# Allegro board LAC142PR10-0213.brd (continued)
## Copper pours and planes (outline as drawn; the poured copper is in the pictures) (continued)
LX_VDDP_ALWP on TOP (solid shape): 140.26,149.1 140.26,148.27 140.2,148.21 138.36,148.21 138.23,148.34 137.28,148.34 137.22,148.4 137.22,148.59 137.28,148.65 138.23,148.65 138.3,148.72 139.38,148.72 139.57,148.91 139.57,149.1 139.63,149.16 140.2,149.16
LX_VDDP_ALWP on BOTTOM (solid shape): outline of 157 points within 134.68,129.03 146.87,141.48
LX_VDDP_ALWP on IN2 (solid shape): 139.38,148.59 139.38,147.7 139.06,147.38 138.68,147.38 138.23,147.83 138.23,148.59 138.36,148.72 139.25,148.72
LX_VDDP_ALWP on IN2 (solid shape): 140.26,135.32 140.26,134.75 140.14,134.62 139.12,134.62 138.99,134.75 138.99,135.83 139.19,136.02 139.57,136.02
PHASE_CHG on BOTTOM (solid shape): 135.76,167.32 135.76,162.94 136.45,162.24 137.15,162.24 137.41,161.99 137.41,159.83 137.15,159.58 133.47,159.58 133.15,159.89 133.15,165.42 132.71,165.86 131.57,165.86 131.44,165.99 131.44,167.45 131.63,167.64 135.44,167.64
PHASE_CHG on BOTTOM (solid shape): 119.88,167.08 120.04,167.08 120.12,167.07 120.21,167.08 120.95,167.08 120.95,167.08 121.98,167.08 122,167.06 122,166.19 121.98,166.17 121.31,166.17 120.97,166.5 120.06,166.5 119.6,166.96 118.58,166.96 118.54,167.01 118.54,167.12 118.6,167.18 119.77,167.18
PHASE_CHG on IN2 (solid shape): 133.66,163.58 133.66,162.69 133.53,162.56 132.9,162.56 132.39,163.07 132.39,163.45 132.64,163.7 133.53,163.7
PHASE_CHG on IN2 (solid shape): 121.41,166.94 121.89,166.94 121.96,166.87 121.96,166.26 121.86,166.16 121.51,166.16 121.18,166.5 120.01,166.5 119.88,166.62 119.88,166.88 120.01,167 121.34,167
RING2 on BOTTOM (solid shape): 189.3,21.14 189.3,20.25 189.24,20.19 188.17,20.19 188,20.35 188,21.21 188.11,21.32 189.13,21.32
RING2 on BOTTOM (solid shape): 182.14,18.22 182.14,17.74 183.13,16.75 183.13,15.43 183.08,15.38 182.96,15.38 182.91,15.43 182.91,16.21 182.67,16.45 182.56,16.45 182.21,16.79 181.49,16.79 180.81,17.47 180.81,17.48 180.75,17.54 180.75,18.22 180.86,18.33 182.02,18.33
RING2 on IN2 (solid shape): 182.94,18.92 182.94,18.54 182.56,18.16 182.56,17.53 182.17,17.14 181.79,17.14 181.54,17.4 181.54,18.67 182.17,19.3 182.56,19.3
RING2 on IN2 (solid shape): 188.68,21.21 188.68,20.33 188.55,20.2 187.79,20.2 187.73,20.26 187.67,20.26 187.23,20.7 187.23,21.16 187.38,21.31 188.58,21.31
RING2_R on TOP (solid shape): 192.65,24.78 192.65,23.72 192.35,23.42 190.66,23.42 190.37,23.14 190.37,22.46 190.62,22.21 190.62,21.71 190.58,21.67 190.47,21.51 190.43,21.32 190.43,21.3 190.34,21.21 189.39,21.21 189.2,21.4 189.2,24.62 189.65,25.06 192.37,25.06
RING2_R on BOTTOM (solid shape): 190.47,21.76 190.47,20.59 190.12,20.25 189.5,20.25 189.48,20.27 189.48,21.24 189.3,21.43 189.3,21.68 189.47,21.86 190.37,21.86
SLEEVE on BOTTOM (solid shape): 192.78,14.96 192.78,13.82 192.66,13.7 191.73,13.7 191.62,13.81 191.62,15.03 191.73,15.14 192.6,15.14
SLEEVE on BOTTOM (solid shape): 183.53,20.29 183.53,19.69 183.43,19.58 183.43,17.35 183.56,17.22 183.56,15.47 183.46,15.37 183.38,15.37 183.29,15.46 183.29,16.79 182.4,17.68 182.4,20.13 182.73,20.46 183.37,20.46
SLEEVE on IN1 (solid shape): 184.44,18.37 184.44,17.43 184.31,17.29 183.04,17.29 182.91,17.42 182.91,18.34 183.05,18.48 184.34,18.48
SLEEVE on IN1 (solid shape): 192.82,15.36 192.82,14.59 192.66,14.42 191.7,14.42 191.36,14.76 190.61,14.76 190.46,14.91 190.46,15.75 190.51,15.8 192.39,15.8
SLEEVE_R on TOP (solid shape): 193,13.7 193,13.03 192.74,12.77 190.56,12.77 190.41,12.92 190.41,13.82 190.51,13.93 192.77,13.93
SLEEVE_R on TOP (solid shape): 192.39,27 192.39,26.61 192.33,26.55 192.33,26.12 192.68,25.78 193,25.78 193,25.78 193.61,25.78 193.92,25.47 193.92,25.03 193.81,24.92 192.81,24.92 192.3,25.43 191.23,25.43 190.98,25.67 190.98,26.95 191.12,27.08 192.31,27.08
SLEEVE_R on BOTTOM (solid shape): 192.72,13.54 192.72,13.08 192.64,13 190.68,13 190.48,13.21 190.48,13.44 190.63,13.59 192.67,13.59
SNB_1.35VGPU on BOTTOM (solid shape): 192.47,163.02 192.47,162.13 192.78,161.82 193.81,161.82 193.94,161.7 193.94,160.74 193.87,160.68 191.22,160.68 191.06,160.84 191.06,162.7 191.39,163.03 192.46,163.03
SPK_L+_CONN on TOP (solid shape): 90.13,10.43 90.13,9.24 90.04,9.14 89.44,9.14 88.97,9.61 88.37,9.61 87.68,8.93 86.14,8.93 85.3,9.77 83.97,9.77 83.45,9.25 82.1,9.25 81.87,9.01 81.87,7.35 81.76,7.24 80.72,7.24 80.57,7.4 80.57,9.65 81.63,10.72 89.85,10.72
SPK_L+_CONN on BOTTOM (solid shape): 81.88,7.93 81.88,7.01 81.79,6.92 79.2,6.92 78.89,7.24 77.36,7.24 77.18,7.42 77.18,7.67 77.39,7.87 78.92,7.87 79.01,7.96 81.84,7.96
SPK_L-_CONN on TOP (solid shape): 83.17,8.81 83.17,8.16 83.49,7.85 85.19,7.85 85.95,8.61 87.08,8.61 88.26,7.43 89.06,7.43 89.49,7.86 90.11,7.86 90.14,7.84 90.14,6.85 89.83,6.54 82.41,6.54 82.03,6.93 82.03,8.8 82.17,8.95 83.03,8.95
SPK_L-_CONN on BOTTOM (solid shape): 83.15,9.19 83.15,8.35 83.06,8.27 77.37,8.27 77.17,8.47 77.17,8.71 77.37,8.92 78.56,8.92 79.01,9.37 82.97,9.37
SPK_R+_CONN on TOP (solid shape): 90.14,6.13 90.14,5.21 90.05,5.12 89.45,5.12 89.13,5.44 88.16,5.44 87.51,4.79 85.58,4.79 85.24,5.13 83.59,5.13 82.9,4.44 82.06,4.44 81.94,4.57 81.94,5.99 82.3,6.35 89.92,6.35
SPK_R+_CONN on BOTTOM (solid shape): 79.48,5.01 82.86,5.01 83.02,4.86 83.02,3.92 82.84,3.74 79.06,3.74 77.55,5.25 77.32,5.25 77.17,5.4 77.17,5.72 77.35,5.89 78.59,5.89
SPK_R-_CONN on TOP (solid shape): 81.77,5.79 81.77,5.5 81.77,4.28 82.02,4.03 83.82,4.03 84.05,3.79 84.36,3.71 84.87,3.71 85.18,3.79 85.4,4.03 87.49,4.03 88.11,3.4 88.93,3.4 89.34,3.81 90.09,3.81 90.13,3.77 90.13,2.82 90.04,2.73 84.88,2.73 84.66,2.51 82.96,2.51 82.75,2.73 81.21,2.73 80.32,3.63 80.32,5.81 80.48,5.98 81.58,5.98
SPK_R-_CONN on BOTTOM (solid shape): 79.13,6.69 81.32,6.69 81.56,6.46 81.56,5.5 81.44,5.38 79.57,5.38 78.71,6.24 77.35,6.24 77.18,6.4 77.18,6.73 77.31,6.86 78.96,6.86
T-GND_L on TOP (solid shape): 16.22,172.15 16.22,170.13 16.01,169.93 14.97,169.93 14.86,170.04 14.86,172.04 15.09,172.26 16.11,172.26
T-GND_L on BOTTOM (solid shape): 16.12,172.12 16.12,170.12 15.96,169.95 15.11,169.95 15.04,170.01 15.04,172.14 15.17,172.26 15.98,172.26
T-GND_L on BOTTOM (solid shape): 20.44,164.34 20.44,162.12 20.38,162.05 19.36,162.05 19.23,162.18 19.23,164.4 19.3,164.47 20.31,164.47
T-GND_L on IN1 (solid shape): 16.31,172.32 16.31,170.63 16.11,170.43 15.15,170.43 14.9,170.68 14.9,172.25 15.06,172.41 16.23,172.41
T-GND_L on IN1 (solid shape): 20.58,164.92 20.58,163.96 20.44,163.82 19.37,163.82 19.17,164.02 19.17,164.02 19.04,164.15 19.04,165.39 19.29,165.64 19.87,165.64
UG1_APU on TOP (solid shape): 118.04,142.49 118.04,141.6 117.91,141.48 116.9,141.48 116.64,141.73 116.64,142.62 116.9,142.88 117.66,142.88
UG1_APU on TOP (solid shape): 117.27,152.68 117.27,150.47 117.14,150.33 116.9,150.33 116.81,150.42 116.81,151.27 117.05,151.52 117.05,152.69 117.11,152.75 117.2,152.75
UG1_APU on IN2 (solid shape): 117.28,151.26 117.28,149.61 117.15,149.48 116.64,149.48 116.52,149.61 116.52,150.11 116.77,150.37 116.77,151.26 116.9,151.38 117.15,151.38
UG1_APU on IN2 (solid shape): 118.42,142.88 118.42,142.62 118.04,142.24 116.77,142.24 116.64,142.37 116.64,142.75 116.77,142.88 117.4,142.88 117.79,143.26 118.04,143.26
UG1_GFX on TOP (solid shape): 61.78,47.5 61.78,47.12 61.02,46.35 61.02,45.72 60.89,45.59 60.51,45.59 60.38,45.72 60.38,47.5 60.64,47.75 61.52,47.75
UG1_GFX on TOP (solid shape): 61.4,39.62 61.4,38.73 60.89,38.23 60.89,37.27 60.81,37.2 60.71,37.2 60.64,37.27 60.64,38.42 60.89,38.67 60.89,39.62 61.02,39.75 61.27,39.75
UG1_GFX on IN2 (solid shape): 61.08,46.67 61.08,44.96 61.02,44.89 60.45,44.89 60.32,45.02 60.32,46.61 60.57,46.86 60.89,46.86
UG1_GFX on IN2 (solid shape): 62.03,40.51 62.03,40.07 61.4,39.43 61.4,38.73 61.27,38.61 61.02,38.61 60.89,38.73 60.89,39.69 61.27,40.07 61.27,40.51 61.33,40.58 61.97,40.58
UG1_VGA on BOTTOM (solid shape): 177.22,103 177.22,102.68 176.97,102.43 176.52,102.43 175.89,101.79 175.06,101.79 174.87,101.98 174.87,102.17 175.06,102.36 175.32,102.36 176.14,103.19 177.03,103.19
UG1_VGA on BOTTOM (solid shape): 175,94.07 175,93.8 174.88,93.68 174.02,93.68 173.51,93.17 172.38,93.17 172.3,93.25 172.3,93.33 172.37,93.39 172.99,93.39 172.99,93.39 173.3,93.39 174.09,94.19 174.88,94.19
UG1_VGA on IN2 (solid shape): 176.02,102.11 176.02,101.98 175.06,101.03 174.75,101.03 174.43,101.35 174.43,101.66 175.06,102.3 175.82,102.3
UG1_VGA on IN2 (solid shape): 175,94.55 175,93.85 174.83,93.69 174.02,93.69 173.92,93.79 173.92,94.61 174.17,94.87 174.68,94.87
UG2_VGA on BOTTOM (solid shape): 178.24,89.41 178.24,88.84 178.17,88.77 177.73,88.77 177.54,88.96 176.59,88.96 176.46,89.09 176.46,89.41 176.59,89.53 178.11,89.53
UG2_VGA on BOTTOM (solid shape): 196.02,87.44 196.02,86.99 195.89,86.87 195.51,86.87 194.87,86.23 194.68,86.23 194.37,86.55 194.37,86.99 194.94,87.57 195.89,87.57
UG2_VGA on BOTTOM (solid shape): 174.06,90.25 174.6,90.25 174.81,90.04 174.81,89.79 174.68,89.66 173.82,89.66 173.69,89.79 173.69,90.15 173.47,90.37 172.37,90.37 172.31,90.43 172.31,90.54 172.37,90.59 173.71,90.59
UG2_VGA on IN2 (solid shape): 175.19,89.6 177.48,89.6 177.67,89.41 177.67,88.96 177.54,88.84 174.62,88.84 173.67,89.79 173.67,89.98 173.86,90.17 174.62,90.17
UG_1.35V on TOP (solid shape): 63.94,21.08 63.94,20.83 63.81,20.7 62.92,20.7 62.67,20.95 61.78,20.95 61.72,21.02 61.72,21.15 61.78,21.21 63.81,21.21
UG_1.35V on BOTTOM (solid shape): 71.99,19.81 71.99,18.9 71.87,18.77 71,18.77 70.84,18.94 70.84,19.89 71.03,20.08 71.72,20.08
UG_1.35V on IN2 (solid shape): 64.7,21.27 64.7,20.83 64.57,20.7 62.92,20.7 62.79,20.83 62.79,21.08 63.18,21.46 64.51,21.46
UG_1.35V on IN2 (solid shape): 71.37,19.88 71.37,19.05 71.24,18.92 70.99,18.92 70.86,19.05 70.86,19.24 70.16,19.94 70.16,20.13 70.54,20.51 70.73,20.51
UG_3V on TOP (solid shape): 35.87,42.67 35.87,41.78 35.74,41.66 35.11,41.66 34.85,41.91 34.85,42.67 34.98,42.8 35.74,42.8
UG_3V on TOP (solid shape): 40.95,50.04 40.95,49.91 40.25,49.21 39.3,49.21 39.17,49.34 39.17,49.59 39.36,49.78 39.62,49.78 39.93,50.1 40.89,50.1
UG_3V on IN2 (solid shape): 35.87,43.43 35.87,41.78 35.74,41.66 35.43,41.66 35.3,41.78 35.3,42.67 35.11,42.86 35.11,43.43 35.24,43.56 35.74,43.56
UG_3V on IN2 (solid shape): 40.32,49.66 40.32,49.34 39.74,48.77 39.74,48.58 39.49,48.32 39.3,48.32 39.05,48.58 39.05,49.47 39.3,49.72 40.25,49.72
UG_5V on TOP (solid shape): 45.01,42.67 45.01,41.78 44.89,41.66 44.13,41.66 43.87,41.91 43.87,42.67 44,42.8 44.89,42.8
UG_5V on TOP (solid shape): 44.76,49.59 44.76,49.34 44.63,49.21 43.62,49.21 42.89,49.94 42.89,50.04 42.96,50.1 44.25,50.1
UG_5V on IN2 (solid shape): 45.08,43.4 45.08,41.75 44.95,41.62 44.63,41.62 44.51,41.75 44.51,42.77 44.32,42.96 44.32,43.4 44.38,43.47 45.01,43.47
UG_5V on IN2 (solid shape): 45.71,49.34 45.71,49.02 45.52,48.83 45.08,48.83 44.7,49.21 43.74,49.21 43.62,49.34 43.62,49.59 43.74,49.72 45.33,49.72
UG_NB on TOP (solid shape): 121.9,153.36 122.88,153.36 123.02,153.22 123.02,152.98 122.89,152.85 122.04,152.85 121.68,153.21 120.6,153.21 120.54,153.26 120.54,153.36 120.6,153.42 121.84,153.42
UG_NB on BOTTOM (solid shape): 124.33,141.67 124.33,140.02 124.07,139.76 123.69,139.76 123.5,139.95 123.5,141.6 123.75,141.86 124.14,141.86
UG_NB on IN2 (solid shape): 122.95,153.25 122.95,152.16 122.7,151.9 122.14,151.9 121.9,152.14 121.9,153.22 122.02,153.34 122.87,153.34
UG_NB on IN2 (solid shape): 124.96,141.03 124.96,140.91 124.2,140.14 124.2,139.95 124.07,139.83 123.82,139.83 123.69,139.95 123.69,140.84 124.33,141.48 124.52,141.48
UG_VDDP_ALWP on TOP (solid shape): 139.38,149.22 139.38,148.97 139.25,148.84 137.28,148.84 137.22,148.91 137.22,149.1 137.28,149.16 138.17,149.16 138.36,149.35 139.25,149.35
UG_VDDP_ALWP on TOP (solid shape): 145.41,135.64 145.41,135.38 144.96,134.94 144.96,134.05 144.77,133.86 144.39,133.86 144.27,133.98 144.27,135.64 144.39,135.76 145.28,135.76
UG_VDDP_ALWP on IN2 (solid shape): 145.41,135.95 145.41,135.38 145.22,135.19 144.33,135.19 144.14,135.38 144.14,136.4 144.33,136.59 144.77,136.59
UG_VDDP_ALWP on IN2 (solid shape): 140.2,149.29 140.2,148.97 139.95,148.72 139.63,148.72 139.5,148.84 138.36,148.84 138.23,148.97 138.23,149.22 138.42,149.42 140.07,149.42
UGATE_CHG on BOTTOM (solid shape): 132.58,162.94 132.58,161.86 132.45,161.73 131.57,161.73 131.44,161.86 131.44,162.94 131.57,163.07 132.45,163.07
UGATE_CHG on BOTTOM (solid shape): 119.97,166.37 120.81,166.37 120.95,166.23 120.95,166 120.82,165.88 120.04,165.88 119.44,166.47 119.44,166.47 119.35,166.56 118.59,166.56 118.54,166.61 118.54,166.72 118.58,166.77 119.57,166.77
UGATE_CHG on IN2 (solid shape): 121.53,165.93 121.53,165.61 121.21,165.29 121.02,165.29 120.45,165.86 120.01,165.86 119.88,165.99 119.88,166.24 120.01,166.37 121.09,166.37
UGATE_CHG on IN2 (solid shape): 131.37,162.31 132.45,162.31 132.58,162.18 132.58,161.86 132.45,161.73 130.8,161.73 130.74,161.8 130.74,162.43 130.8,162.5 131.18,162.5
VSUMP_NB on TOP (solid shape): 122.12,157.67 122.12,157.2 122.13,157.19 121.98,157.04 121.75,157.04 121.57,156.86 121.57,156.47 121.49,156.4 120.6,156.4 120.53,156.47 120.53,156.55 120.6,156.62 120.9,156.62 121.6,157.32 121.6,157.65 121.72,157.77 122.01,157.77
N17205206 on BOTTOM (solid shape): 186.37,35.81 186.37,35.12 184.4,33.15 184.27,33.15 184.21,33.21 184.21,34.29 184.37,34.45 184.81,34.45 185.73,35.37 185.73,35.81 185.79,35.88 186.3,35.88
N17382859 on BOTTOM (solid shape): 32.96,51.39 33.41,51.39 33.41,51.88 33.76,51.88 33.76,51.39 34.21,51.39 34.21,51.88 34.66,51.88 34.79,51.75 34.79,50.67 33.71,49.59 33.71,48.32 33.65,48.26 30.66,48.26 30.47,48.45 30.47,50.16 32.19,51.88 32.96,51.88
N17415515 on TOP (solid shape): outline of 103 points within 94.88,157.29 98.84,162.65
N17451409 on TOP (solid shape): 67.93,51.23 68.6,51.23 68.6,50.67 69.14,50.67 69.14,51.22 69.4,51.22 69.4,50.69 69.94,50.69 69.94,51.23 72.57,51.23 72.8,51 72.8,46.35 72.36,45.91 66.22,45.91 65.78,45.47 62.67,45.47 62.54,45.59 62.54,53.21 63.07,53.75 65.41,53.75
N17481633 on BOTTOM (solid shape): 130.36,171.45 130.36,168.15 130.87,167.64 130.87,160.59 130.49,160.21 129.63,160.21 129.63,160.7 128.98,160.7 128.98,160.21 128.43,160.21 128.43,160.7 127.78,160.7 127.78,160.21 127.18,160.21 127.06,160.34 127.06,164.08 127.44,164.47 127.44,171.45 127.5,171.51 130.3,171.51
N19198957 on TOP (solid shape): 19.69,79.68 19.69,79.11 19.51,78.93 17.67,78.93 16.49,80.11 14.75,80.11 14.55,80.31 14.55,81.6 14.65,81.7 17.67,81.7
N20135074 on BOTTOM (solid shape): 177.48,98.36 178.49,98.36 178.56,98.3 178.56,97.73 178.49,97.66 175.44,97.66 175.38,97.73 175.38,98.68 175.44,98.74 177.09,98.74
N20135197 on BOTTOM (solid shape): 189.29,106.36 189.99,105.66 189.99,104.01 188.97,104.01 188.91,104.08 188.91,105.79 188.65,106.04 188.65,106.93 189.29,106.93
N20141406 on TOP (solid shape): 118.47,152.68 118.47,151.63 119.13,150.97 119.13,147.86 119.06,147.79 118.54,147.79 118.46,147.87 118.46,150.06 118.58,150.18 118.58,151.23 118.25,151.55 118.25,152.66 118.33,152.74 118.41,152.74
N20141477 on BOTTOM (solid shape): 133.29,139.63 133.29,137.2 132.94,136.85 131.62,136.85 131.31,137.15 131.31,139.31 131.78,139.78 133.14,139.78
N20141719 on TOP (solid shape): 120.2,144.14 120.2,142.43 120.14,142.37 118.48,142.37 118.42,142.43 118.42,144.27 118.74,144.59 119.75,144.59
N20272996 on TOP (solid shape): 59.94,40.83 59.94,39.94 59.87,39.88 59.49,39.88 59.37,39.75 59.37,38.73 59.67,38.43 59.67,37.25 59.62,37.2 59.51,37.2 59.45,37.25 59.45,38.27 58.86,38.86 58.86,40.51 59.24,40.89 59.87,40.89
N20273046 on BOTTOM (solid shape): 73.78,47.88 73.78,46.16 73.34,45.72 72.26,45.72 72,45.97 72,47.88 72.13,48.01 73.65,48.01
N20273223 on TOP (solid shape): 57.4,35.06 57.4,34.19 57.32,34.11 56.13,34.11 56.03,34.21 56.03,35.06 56.11,35.13 57.33,35.13
N20277901 on BOTTOM (solid shape): 136.45,141.54 136.45,139.64 136.39,139.57 134.74,139.57 134.68,139.64 134.68,140.65 134.8,140.78 135.5,140.78 135.69,140.97 135.69,141.54 135.76,141.6 136.39,141.6
N20391331 on TOP (solid shape): 32.96,9.98 33.41,9.98 33.41,10.48 33.76,10.48 33.76,9.98 34.21,9.98 34.21,10.48 35.43,10.48 38.28,7.62 38.28,4.38 38.22,4.32 35.87,4.32 35.74,4.44 35.74,7.05 35.55,7.24 32.38,7.24 32.31,7.3 32.31,10.22 32.57,10.48 32.96,10.48
N20394075 on TOP (solid shape): 199.07,138.18 199.07,137.6 198.57,137.6 198.57,137.14 199.07,137.14 199.07,136.8 198.57,136.8 198.57,136.34 199.07,136.34 199.07,135.51 198.88,135.32 197.29,135.32 197.03,135.57 197.03,137.92 197.41,138.3 198.94,138.3
N20394075 on BOTTOM (solid shape): 198.43,137.6 198.43,132.4 198.18,132.14 196.97,132.14 196.91,132.21 196.91,133.03 196.78,133.16 196.78,135.19 196.4,135.57 193.8,135.57 193.73,135.64 193.73,138.11 193.8,138.18 197.86,138.18
N20395535 on BOTTOM (solid shape): 157.03,42.93 157.03,41.97 157.79,41.21 157.79,37.97 157.6,37.78 157.15,37.78 157.15,38.28 156.69,38.28 156.69,37.78 156.35,37.78 156.35,38.28 155.89,38.28 155.89,37.78 155.38,37.78 155.19,37.97 155.19,39.18 156.2,40.2 156.2,41.53 156.71,42.04 156.71,42.93 156.77,42.99 156.97,42.99
N20395548 on BOTTOM (solid shape): 154.36,45.21 154.36,44.32 154.74,43.94 154.74,43.43 154.62,43.31 154.23,43.31 153.47,44.07 153.47,45.21 153.6,45.34 154.23,45.34
N20623473 on BOTTOM (solid shape): 24.54,14.28 24.54,13.35 25.17,12.72 25.17,11.91 24.97,11.7 23.78,11.7 23.43,12.05 23.43,12.96 23.7,13.24 23.7,14.28 23.83,14.4 24.42,14.4
N21017384 on BOTTOM (solid shape): 123.44,167.07 123.44,164.78 123.37,164.72 122.74,164.72 122.68,164.78 122.68,167.07 122.74,167.13 123.37,167.13
N21022260 on TOP (solid shape): 125.3,154.5 125.3,152.24 125.18,152.12 124.58,152.12 124.47,152.23 124.47,153.22 124.38,153.31 124.38,154.45 124.57,154.64 125.15,154.64
N21022300 on TOP (solid shape): 118.21,148.62 118.21,148.07 118.1,147.96 115.95,147.96 115.87,148.03 115.87,148.67 115.94,148.73 118.1,148.73
N21023084 on TOP (solid shape): 63.56,40.83 63.56,40.2 63.49,40.13 62.54,40.13 62.29,39.88 61.65,39.88 61.59,39.94 61.59,40.77 61.72,40.89 63.49,40.89
N21024525 on BOTTOM (solid shape): 176.33,89.98 176.33,88.07 176.21,87.95 175.6,87.95 175.46,88.09 175.46,88.9 175.32,89.04 175.32,89.98 175.38,90.04 176.27,90.04
N21024549 on BOTTOM (solid shape): 176.32,95.74 176.32,93.88 176.18,93.74 175.34,93.74 175.23,93.85 175.23,94.56 175.46,94.79 175.46,95.7 175.6,95.83 176.23,95.83
N27700813 on TOP (solid shape): 26.35,70.1 26.35,62.36 25.71,61.72 25.2,61.72 25.08,61.85 25.08,63.9 24.24,64.73 24.24,67.49 25.2,68.45 25.2,70.36 25.33,70.48 25.96,70.48
N28237059 on BOTTOM (solid shape): 198.24,171.59 198.24,171.2 197.36,170.31 197.36,169.58 196.91,169.13 196.91,166.94 197.73,166.12 197.73,164.78 197.67,164.72 197.48,164.72 197.41,164.78 197.41,165.73 196.21,166.94 196.21,167.16 196.26,167.34 196.21,167.51 196.21,171.39 196.45,171.63 198.2,171.63
N28484451 on TOP (solid shape): 141.57,159.18 141.57,158.66 141.24,158.33 141.24,156.92 141.1,156.78 139.46,156.78 139.21,157.04 139.21,159.09 139.4,159.28 141.47,159.28
N28714507 on TOP (solid shape): 75.06,170.54 75.06,169.3 75.61,168.76 76.45,168.76 77.88,167.32 77.88,166.23 77.86,166.2 77.39,166.2 76.5,165.32 74.57,165.32 74.42,165.47 74.42,166.38 74.22,166.57 74.01,166.57 74.01,166.79 73.84,167.3 73.68,166.79 73.68,166.57 71.82,166.57 71.55,166.85 71.55,170.52 71.85,170.83 74.77,170.83
N28714606 on BOTTOM (solid shape): 132.52,165.54 132.52,163.77 132.45,163.7 131.57,163.7 131.44,163.83 131.44,165.54 131.57,165.67 132.39,165.67
N28714612 on BOTTOM (solid shape): 119.77,166 119.78,165.99 119.86,165.86 119.98,165.78 119.99,165.78 120.05,165.72 121.97,165.72 122.01,165.67 122.01,164.81 121.93,164.72 120.33,164.72 120.05,165 120.04,165.02 119.95,165.21 119.76,165.3 119.74,165.3 118.88,166.16 118.59,166.16 118.53,166.22 118.53,166.31 118.6,166.37 119.4,166.37
N28714617 on TOP (solid shape): 78.11,175.67 78.11,171.69 77.67,171.25 71.54,171.25 71,171.79 71,175.82 71.23,176.05 77.73,176.05
N28714617 on BOTTOM (solid shape): 110.86,177.93 110.86,177.29 109.34,177.29 109.34,176.66 110.86,176.66 110.86,175.64 108.11,172.89 76.49,172.89 76.1,173.27 76.1,176.11 76.43,176.44 106.5,176.44 108.04,177.99 110.8,177.99
N28714637 on TOP (solid shape): 135.69,177.42 135.69,175.89 135.44,175.64 133.15,175.64 133.03,175.77 133.03,176.28 133.15,176.4 134.42,176.4 134.8,176.78 134.8,177.42 134.93,177.55 135.57,177.55
N28714684 on TOP (solid shape): 72.85,166.07 72.85,165.09 72.69,164.92 71.47,164.92 70.81,164.26 70.81,163.35 70.66,163.19 69.75,163.19 69.6,163.35 69.6,164.49 69.74,164.63 70.14,164.63 70.5,165 70.5,165.89 70.78,166.17 72.75,166.17
N28714693 on TOP (solid shape): 138.11,175.26 138.11,174.56 136.58,174.56 136.58,173.93 138.11,173.93 138.11,172.02 137.92,171.83 133.22,171.83 133.03,172.02 133.03,175.01 133.34,175.32 138.04,175.32
N28714693 on BOTTOM (solid shape): 137.72,157.48 137.72,153.99 137.28,153.54 133.53,153.54 133.28,153.8 133.28,157.48 133.53,157.73 137.47,157.73
N28714693 on IN1 (solid shape): outline of 485 points within 133.03,155.96 146.23,175.89
N47415217 on TOP (solid shape): 37.2,51.63 37.2,49.47 37.14,49.4 36.51,49.4 36.44,49.47 36.44,51.63 36.51,51.69 37.14,51.69
N47415258 on BOTTOM (solid shape): 34.85,44.32 34.85,42.42 34.79,42.35 33.2,42.35 33.14,42.42 33.14,43.43 33.2,43.5 34.09,43.5 34.28,43.69 34.28,44.32 34.35,44.39 34.79,44.39
N47415272 on BOTTOM (solid shape): 42.67,44.26 42.67,43.75 42.86,43.56 43.55,43.56 43.81,43.31 43.81,42.42 43.68,42.29 42.16,42.29 42.09,42.35 42.09,44.26 42.16,44.32 42.6,44.32
N47415370 on TOP (solid shape): 47.68,51.56 47.68,49.4 47.62,49.34 46.98,49.34 46.92,49.4 46.92,51.56 46.98,51.63 47.62,51.63
N47420895 on BOTTOM (solid shape): 74.07,14.16 74.07,13.46 74.19,13.33 74.96,13.33 75.02,13.27 75.02,12.76 74.7,12.45 72.99,12.45 72.92,12.51 72.92,14.16 72.99,14.22 74,14.22

Small or netless copper shapes (teardrops, artwork), in the pictures only: 82 on TOP, 20 on BOTTOM

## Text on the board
Ref Des/Silkscreen Bottom: H7 | H21 | H23 | H6 | H22 | DIMMB | DIMMA | SODIMM-ONLY | SUPPORT DDR3L | M2X3L | NGFF
User.Comments: LAC142P | 2016-02-13 | 2015-02-13 | AAL12 | Win
User.38: FIGURE | SIZE | 8.0 | 22.0 | 24.0 | 28.0 | 35.0 | 39.0 | 118.0 | 126.0 | 130.0 | 134.0 | 146.0 | 31.0 | 43.0 | 47.0 | 55.0 | 63.0 | 67.0 | 157.0 | 63.0x35.0 | 67.0x35.0 | 94.0x24.0 | 94.0x28.0 | 94.0x35.0 | 112.0x31.0 | 134.0x24.0 | 150.0x118.0 | DRILL CHART: TOP to BOTTOM | ALL UNITS ARE IN MILS | TOLERANCE | +3.0/-3.0 | +2.0/-2.0 | PLATED | NON-PLATED | QTY | 5057 | 19 | 15 | 9 | 8 | 5 | 2 | 3 | 1 | 6
